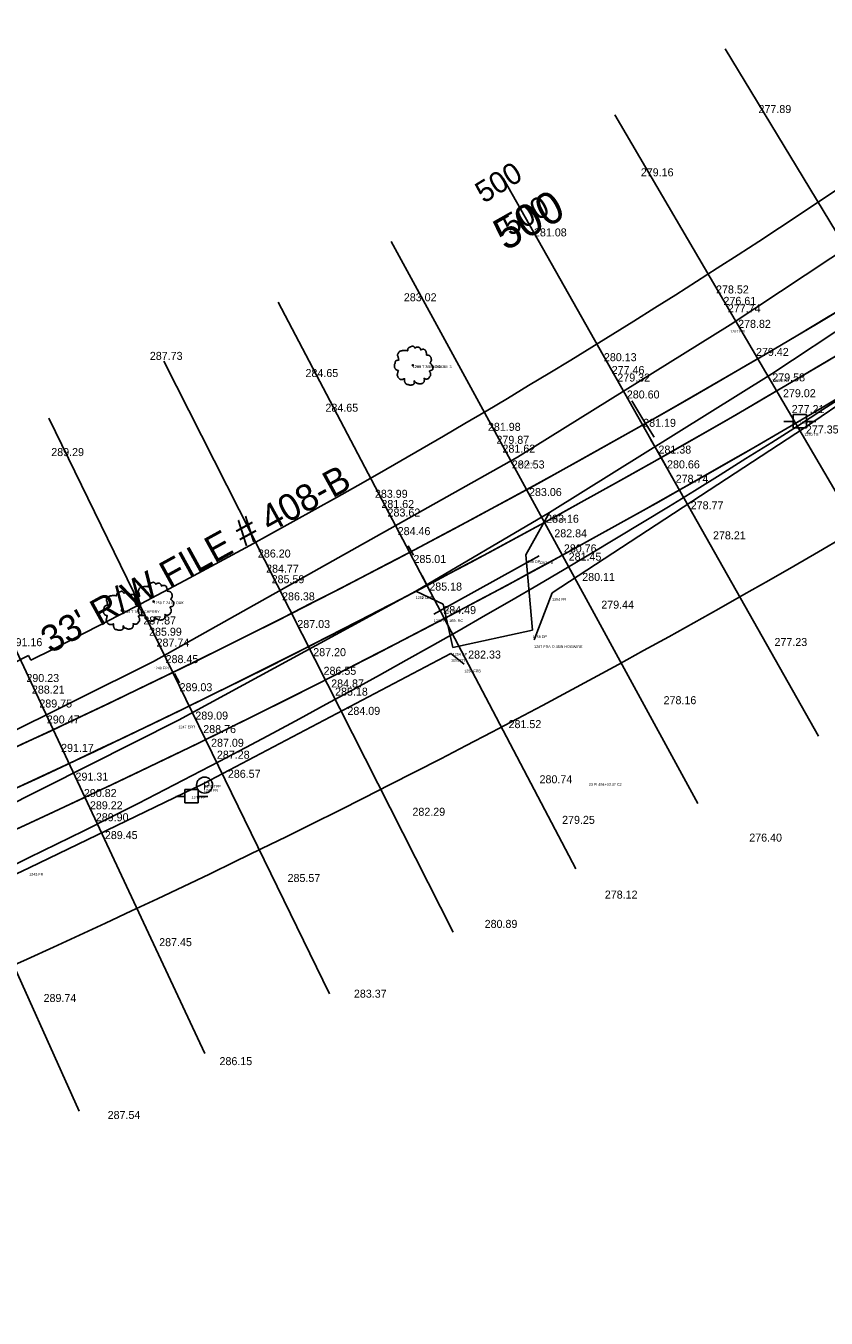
# Model space of a CAD drawing. Extents: x 49683 to 58852, y 49525 to 54803.
# Drawn here: x 51912.8 to 52213, y 50048.4 to 50532.8 of the extents above; entities that cross this region are included whole.
import ezdxf

# ---------------------------------------------------------------- set-up
doc = ezdxf.new("R2010")
doc.units = 0
for name, color, linetype in [('Level 1', 7, 'Continuous'), ('Level 11', 7, 'Continuous'), ('Level 13', 7, 'Continuous'), ('Level 19', 7, 'Continuous'), ('Level 20', 7, 'Continuous'), ('Level 21', 7, 'Continuous'), ('Level 25', 7, 'Continuous'), ('Level 29', 7, 'Continuous'), ('Level 3', 7, 'Continuous'), ('Level 32', 7, 'Continuous'), ('Level 33', 7, 'Continuous'), ('Level 50', 7, 'Continuous'), ('Level 51', 7, 'Continuous'), ('Level 53', 7, 'Continuous'), ('Level 56', 7, 'Continuous'), ('Level 58', 7, 'Continuous'), ('Level 59', 7, 'Continuous'), ('Level 6', 7, 'Continuous'), ('Level 61', 7, 'Continuous'), ('Level 63', 7, 'Continuous'), ('Level 8', 7, 'Continuous'), ('Level 9', 7, 'Continuous')]:
    doc.layers.add(name, color=color, linetype=linetype)

# ---------------------------------------------------------------- blocks, each defined once
blk = doc.blocks.new('PP')
at = {"layer": 'Level 9'}
for p, q in [((2.53, 2.45), (-2.47, 2.45)), ((-2.47, 2.45), (-2.47, -2.55)), ((2.53, -2.55), (2.53, 2.45)), ((-5.91, -0.11), (-2.44, -0.11)), ((-2.47, -2.55), (2.53, -2.55)), ((2.45, -0.11), (6.09, -0.11))]:
    blk.add_line(p, q, dxfattribs=at)
blk = doc.blocks.new('TPP')
at = {"layer": 'Level 9'}
blk.add_circle((0, 0), 3, dxfattribs=at)
blk.add_text('P', height=3, dxfattribs=at).set_placement((-0.59, -1.73))
blk = doc.blocks.new('T1')
at = {"layer": 'Level 11'}
for centre, radius in [((0, 0), 0.25), ((-0.01, -0.02), 0.0001)]:
    blk.add_circle(centre, radius, dxfattribs=at)
for points in [[(0.13, 7.17), (-0.17, 7.19), (-0.49, 7.09), (-0.74, 6.99), (-0.97, 6.92), (-1.19, 6.82), (-1.49, 6.64), (-1.72, 6.44), (-1.84, 6.19), (-1.89, 5.97), (-1.94, 5.69), (-1.94, 5.52), (-2.07, 5.49), (-2.22, 5.52), (-2.47, 5.59), (-2.72, 5.59), (-2.97, 5.59), (-3.32, 5.57), (-3.67, 5.57), (-3.94, 5.52), (-4.27, 5.47), (-4.64, 5.34), (-4.99, 5.22), (-5.29, 4.97), (-5.54, 4.49), (-5.67, 4.14), (-5.82, 3.89), (-5.67, 3.44), (-5.49, 3.09), (-5.47, 2.89), (-5.39, 2.47), (-5.29, 2.24), (-5.17, 2.04), (-5.24, 2.02), (-5.62, 1.97), (-5.92, 1.87), (-6.34, 1.64), (-6.57, 1.42), (-6.67, 1.09), (-6.69, 0.75), (-6.79, 0.55), (-6.87, 0.27), (-6.89, 0.2), (-6.94, -0.13), (-6.84, -0.58), (-6.82, -0.93), (-6.69, -1.15), (-6.54, -1.33), (-6.37, -1.58), (-5.97, -1.8), (-5.64, -1.9), (-5.44, -1.93), (-5.62, -2.43), (-5.67, -2.78), (-5.79, -3.18), (-5.79, -3.25), (-5.84, -3.73), (-5.69, -4.05), (-5.62, -4.43), (-5.44, -4.65), (-5.17, -4.95), (-4.84, -5.18), (-4.34, -5.3), (-3.94, -5.28), (-3.37, -5.1), (-3.12, -5.03), (-3.14, -5.2), (-3.12, -5.58), (-3.12, -6), (-2.97, -6.33), (-2.87, -6.6), (-2.72, -6.85), (-2.39, -7.08), (-1.99, -7.15), (-1.57, -7.3), (-1.12, -7.38), (-0.62, -7.4), (-0.02, -7.25), (0.26, -7.13), (0.36, -6.95), (0.56, -6.58), (0.51, -6.35), (0.53, -5.75), (0.63, -5.93), (0.81, -6.28), (1.31, -6.58), (1.71, -6.75), (2.18, -6.9), (2.48, -6.98), (2.96, -6.9), (3.33, -6.83), (3.71, -6.7), (4.01, -6.43), (4.18, -6.15), (4.23, -5.88), (4.31, -5.5), (4.36, -5.33)], [(4.36, -5.33), (4.28, -5.15), (4.23, -4.9), (4.31, -4.93), (4.48, -4.98), (4.75, -5.1), (4.98, -5.18), (5.3, -5.15), (5.58, -5.05), (6.03, -4.78), (6.3, -4.3), (6.58, -3.9), (6.65, -3.58), (6.6, -3.35), (6.58, -2.85), (6.38, -2.6), (6.33, -2.48), (6.23, -2.08), (6.3, -2.03), (6.58, -1.98), (6.95, -1.85), (7.23, -1.73), (7.45, -1.55), (7.53, -1.33), (7.5, -0.93), (7.55, -0.53), (7.48, -0.38), (7.38, -0.23), (7.3, -0.03), (7.15, 0.12), (7.05, 0.27), (6.95, 0.37), (6.83, 0.52), (6.65, 0.65), (6.5, 0.7), (6.45, 0.85), (6.6, 1.04), (6.65, 1.14), (6.68, 1.37), (6.9, 1.72), (6.95, 2.12), (6.9, 2.54), (6.85, 2.82), (6.7, 3.09), (6.5, 3.34), (6.38, 3.52), (6.2, 3.64), (5.88, 3.77), (5.63, 3.82), (5.28, 3.82), (5.08, 3.87), (5.1, 3.92), (5.1, 4.07), (5.1, 4.34), (5.03, 4.79), (4.88, 5.29), (4.88, 5.32), (4.78, 5.57), (4.56, 5.77), (4.38, 5.87), (4.18, 5.99), (3.93, 6.02), (3.63, 6.02), (3.36, 5.97), (3.16, 5.87), (2.98, 5.74), (2.91, 5.89), (2.81, 6.19), (2.76, 6.34), (2.61, 6.52), (2.38, 6.72), (1.93, 6.84), (1.31, 6.77), (1.01, 6.57), (0.86, 6.39), (0.81, 6.52), (0.61, 6.72), (0.51, 6.89), (0.33, 7.02), (0.18, 7.12), (0.08, 7.17)]]:
    blk.add_spline(points, degree=3, dxfattribs=at)

msp = doc.modelspace()

# ---------------------------------------------------------------- linework, layer by layer
at = {"layer": 'Level 1'}
for p, q in [((52144.23, 50385.43), (52140.03, 50392.24)), ((52148.42, 50378.61), (52144.23, 50385.43)), ((52058.19, 50334.47), (52056.21, 50337.95)), ((51970.43, 50286.55), (51968.57, 50290.09))]:
    msp.add_line(p, q, dxfattribs=at)
at = {"layer": 'Level 13'}
msp.add_line((51913.82, 50296.82), (51914.71, 50295.04), dxfattribs=at)
for radius, start, end in [(2897.79, 282.71776, 311.63339), (2831.79, 296.71776, 308.71775), (2829.79, 291.71776, 296.71776)]:
    msp.add_arc((50641.55, 52824.48), radius, start, end, dxfattribs=at)
at = {"layer": 'Level 19'}
for p, q in [((52151.03, 50370.99), (52147.09, 50377.95)), ((52151.03, 50370.99), (52154.97, 50364.02)), ((52063.25, 50323.09), (52061.39, 50326.63)), ((51974.05, 50277.89), (51972.3, 50281.49))]:
    msp.add_line(p, q, dxfattribs=at)
msp.add_arc((50539, 53220.69), 3274.06, 284.51284, 311.63337, dxfattribs=at)
at = {"layer": 'Level 20'}
for radius in [3260.06, 3288.06]:
    msp.add_arc((50539, 53220.69), radius, 284.51284, 311.63318, dxfattribs=at)
at = {"layer": 'Level 29'}
for p, q in [((52151.03, 50370.99), (52147.09, 50377.95)), ((52063.25, 50323.09), (52061.39, 50326.63)), ((51974.05, 50277.89), (51972.3, 50281.49))]:
    msp.add_line(p, q, dxfattribs=at)
msp.add_arc((50539, 53220.69), 3274.06, 284.51246, 311.63337, dxfattribs=at)
at = {"layer": 'Level 3'}
for p, q in [((52176.97, 50420.76), (52262.41, 50477.27)), ((52192.62, 50402.34), (52274.71, 50456.75)), ((52097.21, 50371.15), (52176.97, 50420.76)), ((52109.21, 50350.41), (52192.62, 50402.34)), ((51960.69, 50294.57), (52097.21, 50371.15)), ((52059, 50320.98), (52109.21, 50350.41)), ((51969.98, 50272.55), (52059, 50320.98)), ((51892.1, 50260.44), (51960.69, 50294.57)), ((51902.62, 50238.73), (51969.98, 50272.55))]:
    msp.add_line(p, q, dxfattribs=at)
at = {"layer": 'Level 33'}
msp.add_arc((50539, 53220.69), 3334.06, 284.51246, 308.24612, dxfattribs=at)
at = {"layer": 'Level 50'}
for p, q in [((52175.06, 50524.14), (52299.55, 50318.95)), ((52133.69, 50499.47), (52255.03, 50292.4)), ((52091.94, 50475.43), (52210.11, 50266.54)), ((52049.84, 50452.04), (52164.8, 50241.37)), ((52007.38, 50429.29), (52119.12, 50216.89)), ((51964.59, 50407.19), (52073.06, 50193.11)), ((51921.45, 50385.75), (52026.65, 50170.03)), ((51878, 50364.97), (51979.89, 50147.67)), ((51834.24, 50344.85), (51932.79, 50126.02))]:
    msp.add_line(p, q, dxfattribs=at)
at = {"layer": 'Level 6'}
msp.add_line((52065.82, 50312.34), (52105.27, 50334.14), dxfattribs=at)
at = {"layer": 'Level 63'}
for radius in [3260.06, 3274.06, 3274.06, 3288.06]:
    msp.add_arc((50539, 53220.69), radius, 284.51284, 311.07341, dxfattribs=at)
at = {"layer": 'Level 8'}
for p, q in [((52204.78, 50382.12), (52286.9, 50437.81)), ((52110.13, 50320.32), (52204.78, 50382.12)), ((52100.29, 50334.5), (52109.21, 50350.41)), ((52102.84, 50306.33), (52100.29, 50334.5)), ((52059, 50320.98), (52069.29, 50316.04)), ((52103.43, 50302.65), (52110.13, 50320.32)), ((52069.29, 50316.04), (52072.89, 50299.75)), ((52072.89, 50299.75), (52102.84, 50306.33)), ((51979.55, 50248.78), (52072.23, 50297.54)), ((52072.23, 50297.54), (52077.21, 50293.52)), ((51914.03, 50217.29), (51979.55, 50248.78)), ((51843.63, 50183.86), (51914.03, 50217.29))]:
    msp.add_line(p, q, dxfattribs=at)

# ---------------------------------------------------------------- block references
at = {"layer": 'Level 11'}
for p in [(52057.94, 50405.56), (51960.7, 50317.06), (51948.78, 50313.69)]:
    msp.add_blockref('T1', p, dxfattribs=at)
at = {"layer": 'Level 9'}
for name, p in [('PP', (52203, 50384.66)), ('TPP', (51979.81, 50248.25)), ('PP', (51974.93, 50244.12))]:
    msp.add_blockref(name, p, dxfattribs=at)

# ---------------------------------------------------------------- texts
at = {"layer": 'Level 19'}
msp.add_text('500', height=8, rotation=29.4962, dxfattribs=at).set_placement((52094.38, 50453.83))
at = {"layer": 'Level 21'}
for height, rotation, p in [(8, 31.6368, (52084.53, 50466.1)), (12, 29.4962, (52092.64, 50448.26))]:
    msp.add_text('500', height=height, rotation=rotation, dxfattribs=at).set_placement(p)
at = {"layer": 'Level 25'}
msp.add_text("33' R/W FILE # 408-B", height=10, rotation=28.841, dxfattribs=at).set_placement((51922, 50297.4))
at = {"layer": 'Level 32'}
for s, p in [('277.89', (52187.59, 50500.13)), ('279.16', (52143.44, 50476.41)), ('281.08', (52103.37, 50453.89)), ('283.02', (52054.56, 50429.58)), ('278.52', (52171.66, 50432.5)), ('276.61', (52174.46, 50428.23)), ('277.74', (52176.09, 50425.44)), ('278.82', (52179.95, 50419.62)), ('287.73', (51959.29, 50407.61)), ('280.13', (52129.6, 50407.13)), ('279.42', (52186.65, 50409.09)), ('284.65', (52017.68, 50401.18)), ('277.46', (52132.53, 50402.32)), ('279.32', (52134.64, 50399.48)), ('279.58', (52192.77, 50399.55)), ('280.60', (52138.2, 50393.15)), ('279.02', (52196.77, 50393.62)), ('284.65', (52025.15, 50388.18)), ('277.21', (52200.05, 50387.68)), ('281.19', (52144.34, 50382.52)), ('281.98', (52086.1, 50381.02)), ('277.35', (52205.36, 50380.03)), ('289.29', (51922.32, 50371.56)), ('279.87', (52089.3, 50376.15)), ('281.62', (52091.56, 50372.84)), ('281.38', (52150.07, 50372.49)), ('282.53', (52095.08, 50366.91)), ('280.66', (52153.29, 50366.94)), ('278.74', (52156.52, 50361.55)), ('283.99', (52043.71, 50355.92)), ('281.62', (52046.14, 50352.1)), ('283.06', (52101.51, 50356.58)), ('283.62', (52048.45, 50348.9)), ('278.77', (52162.17, 50351.6)), ('283.16', (52107.93, 50346.57)), ('284.46', (52052.25, 50341.93)), ('282.84', (52111, 50341.11)), ('278.21', (52170.52, 50340.35)), ('286.20', (51999.83, 50333.53)), ('280.76', (52114.58, 50335.45)), ('284.77', (52002.9, 50327.86)), ('285.01', (52058.17, 50331.48)), ('281.45', (52116.38, 50332.35)), ('285.59', (52004.97, 50323.89)), ('280.11', (52121.47, 50324.75)), ('285.18', (52064.11, 50321.15)), ('286.38', (52008.88, 50317.48)), ('279.44', (52128.62, 50314.36)), ('287.87', (51956.84, 50308.44)), ('284.49', (52069.37, 50312.34)), ('285.99', (51959, 50304.22)), ('287.03', (52014.61, 50307.11)), ('291.16', (51906.69, 50300.31)), ('287.74', (51961.81, 50300.15)), ('277.23', (52193.58, 50300.37)), ('288.45', (51965.2, 50293.96)), ('287.20', (52020.58, 50296.56)), ('282.33', (52078.69, 50295.66)), ('286.55', (52024.45, 50289.58)), ('290.23', (51912.99, 50286.87)), ('284.87', (52027.31, 50284.82)), ('288.21', (51915.06, 50282.53)), ('289.03', (51970.45, 50283.44)), ('285.18', (52028.77, 50281.76)), ('289.75', (51917.84, 50277.32)), ('284.09', (52033.4, 50274.57)), ('278.16', (52151.99, 50278.56)), ('290.47', (51920.66, 50271.33)), ('289.09', (51976.36, 50272.8)), ('288.76', (51979.33, 50267.73)), ('281.52', (52093.84, 50269.59)), ('291.17', (51925.99, 50260.69)), ('287.09', (51982.26, 50262.61)), ('287.28', (51984.45, 50258.13)), ('286.57', (51988.56, 50250.97)), ('291.31', (51931.41, 50249.91)), ('280.74', (52105.46, 50248.92)), ('290.82', (51934.55, 50243.76)), ('289.22', (51936.82, 50239.17)), ('282.29', (52057.78, 50236.75)), ('289.90', (51939.03, 50234.69)), ('279.25', (52113.93, 50233.71)), ('289.45', (51942.43, 50228)), ('276.40', (52184.12, 50227.06)), ('285.57', (52010.95, 50211.93)), ('278.12', (52129.94, 50205.7)), ('280.89', (52084.87, 50194.72)), ('287.45', (51962.79, 50187.87)), ('283.37', (52035.83, 50168.56)), ('289.74', (51919.43, 50166.94)), ('286.15', (51985.42, 50143.28)), ('287.54', (51943.46, 50123.1))]:
    msp.add_text(s, height=3, dxfattribs=at).set_placement(p)
at = {"layer": 'Level 51'}
msp.add_text('23 PI 494+33.47 C2', height=1, dxfattribs=at).set_placement((52123.93, 50247.98))
at = {"layer": 'Level 53'}
for s, p in [('1267 EPL', (52176.97, 50417.76)), ('1268 EPR', (52192.62, 50399.34)), ('1265 EPL', (52097.21, 50368.15)), ('1261 EPR', (52109.21, 50347.41)), ('1251 EPR', (52059, 50317.98)), ('1248 EPL', (51960.69, 50291.57)), ('1247 EPR', (51969.98, 50269.55))]:
    msp.add_text(s, height=1, dxfattribs=at).set_placement(p)
at = {"layer": 'Level 56'}
for s, p in [('1263 PB', (52105.27, 50331.14)), ('1262 PA 18IN RC', (52065.82, 50309.34))]:
    msp.add_text(s, height=1, dxfattribs=at).set_placement(p)
at = {"layer": 'Level 58'}
for s, p in [('1270 FR', (52204.78, 50379.12)), ('1260 DPB', (52109.21, 50347.41)), ('1259 DP', (52100.29, 50331.5)), ('1252 DPA', (52059, 50317.98)), ('1264 FR', (52110.13, 50317.32)), ('1253 DP', (52069.29, 50313.04)), ('1258 DP', (52102.84, 50303.33)), ('1254 DP', (52072.89, 50296.75)), ('1257 FRA O 48IN HOGWIRE', (52103.43, 50299.65)), ('1255 FR', (52072.23, 50294.54)), ('1256 FRB', (52077.21, 50290.52)), ('1246 FR', (51979.55, 50245.78)), ('1243 FR', (51914.03, 50214.29))]:
    msp.add_text(s, height=1, dxfattribs=at).set_placement(p)
at = {"layer": 'Level 59'}
for s, p in [('1269 PP', (52203, 50383.66)), ('1244 PP', (51974.93, 50243.12)), ('1245 TPP', (51979.81, 50247.25))]:
    msp.add_text(s, height=1, dxfattribs=at).set_placement(p)
at = {"layer": 'Level 61'}
for s, p in [('1266 T 36 IN OAK', (52057.94, 50404.56)), ('1709 T 36IN OAK BM 3', (52057.94, 50404.56)), ('1250 T 24 IN OAK', (51960.7, 50316.06)), ('1249 T 18 IN CHERRY', (51948.78, 50312.69))]:
    msp.add_text(s, height=1, dxfattribs=at).set_placement(p)

doc.saveas('drawing.dxf')
